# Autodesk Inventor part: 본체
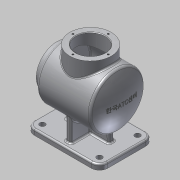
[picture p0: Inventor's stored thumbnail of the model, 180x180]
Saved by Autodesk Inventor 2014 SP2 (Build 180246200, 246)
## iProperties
Created: 2016-09
Part Number: 본체
Material: 알루미늄 6061
Document SubType Name: Modeling
Designer: 1sil_ho3333
Density: 2.71 g/cm^3
Appearance: 알루미늄 - 평지
Mass: 972.342 g
Surface Area: 1283.14 cm^2
Volume: 358.798 cm^3
Author: 1sil_ho3333
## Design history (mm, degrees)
sketch "스케치2"
  geometry: L1 (-61, 0)-(61, 0); L2 (61, 0)-(61, -38); L3 (61, -38)-(49, -38); L4 (49, -38)-(49, -50); L5 (49, -50)-(-49.562, -50); A1 r 115 centre (54, 0) between (-61, 0) and (-49.562, -50); 2 further points
  constraints: 10 end point, 2 parallel, 2 perpendicular, 2 point on circle, 1 centre point, 1 coincident, 1 horizontal, 1 midpoint, 1 point on line
  dimensions: "d4" = 122 distance of L1.start L1.end; "d5" = 100 diameter of L5 L1; "d6" = 76 diameter of L3 L1; "d8" = 115 radius of A1; "d9" = 12 distance of L2.end L3.end
revolve "회전1" sketch "스케치2" stored, may be unused: angle "d10" = 90 deg
node "작업 평면1"
sketch "스케치3"
  geometry: L1 (-67.5, -50)-(67.5, -50); L2 (67.5, -50)-(67.5, 50); L3 (67.5, 50)-(-67.5, 50); L4 (-67.5, 50)-(-67.5, -50); 3 further points
  constraints: 8 end point, 2 midpoint, 2 parallel, 1 horizontal, 1 horizontal alignment, 1 perpendicular, 1 vertical alignment
  dimensions: "d12" = 100 distance of L1.end L2.end; "d13" = 135 distance of L2.end L3.end
extrude "돌출2" join sketch "스케치3" distance "d14" = 10; taper "d15" = 0 deg
node "작업 평면2"
sketch "스케치4"
  geometry: L1 (-61, -38)-(-61, 38) reference; L2 (-61, 0)-(61, 0); L3 (-61, 0)-(-61, 27); L4 (-61, 27)-(-46, 27); L5 (-46, 27)-(-46, 47); L6 (-46, 47)-(47.661, 47); L7 (-49, 50)-(49.562, 50) reference; L8 (-49, -50)-(-49, 50) reference; A1 r 115 centre (-54, 0) between (49.562, -50) and (49.562, 50) reference; A2 r 112 centre (-54, 0) between (58, 0) and (47.661, 47); 1 further point
  constraints: 10 end point, 3 point on circle, 2 perpendicular, 2 point on line, 1 centre point, 1 midpoint, 1 parallel
  dimensions: "d17" = 3 radial gap between concentric circles of A1 A2; "d18" = 3 distance between parallel lines of L7 L6; "d19" = 3 distance between parallel lines of L8 L5; "d20" = 54 diameter of L4 L2
revolve "회전2" sketch "스케치4" stored, may be unused: angle "d21" = 90 deg
fillet "모깎기1" dims "d22" = 2
chamfer "모따기1" distance "d23" = 1; stored, may be unused: second distance "d24" = 2, angle "d25" = 45 deg
sketch "스케치5"
  geometry: L1 (61, 38)-(61, -38) reference; C1 r 38 at (-1, 0); 1 further point
  constraints: 1 centre point
  dimensions: "d26" = 76 diameter of C1; "d28" = 62 distance from line of C1.centre L1
extrude "돌출3" join sketch "스케치5" stored distance "d29" = 10; taper "d30" = 0 deg
sketch "스케치6"
  geometry: C1 r 38 at (0, 0) reference; C2 r 27 at (0, 0); 1 further point
  constraints: 1 centre point, 1 coincident
  dimensions: "d31" = 54 diameter of C2
extrude "돌출4" cut sketch "스케치6" stored distance "d32" = 10; taper "d33" = 0 deg
fillet "모깎기2" dims "d34" = 5
fillet "모깎기3" dims "d35" = 3
chamfer "모따기2" distance "d36" = 1; stored, may be unused: second distance "d37" = 2, angle "d38" = 45 deg
sketch "스케치7"
  geometry: L1 (-40, -5)-(40, -5); L2 (40, -5)-(40, 5); L3 (40, 5)-(-40, 5); L4 (-40, 5)-(-40, -5); L5 (-5, -40)-(5, -40); L6 (5, -40)-(5, 40); L7 (5, 40)-(-5, 40); L8 (-5, 40)-(-5, -40); 5 further points
  constraints: 16 end point, 4 midpoint, 4 parallel, 2 horizontal, 2 horizontal alignment, 2 perpendicular, 2 vertical alignment
  dimensions: "d39" = 10 distance of L6.end L7.end; "d40" = 10 distance of L1.end L2.end; "d41" = 80 distance of L1.start L1.end; "d42" = 80 distance of L5.end L6.end
extrude "돌출6" join sketch "스케치7" stored distance "d45" = 10; taper "d46" = 0 deg
sketch "스케치8"
  geometry: L1 (-40, -72)-(-37.962, -48.7); L2 (-37.962, -48.7)-(37.962, -48.7); L3 (37.962, -48.7)-(40, -72); L4 (40, -72)-(-40, -72); L5 (67.5, -72)-(-67.5, -72) reference; L6 (-44, -50)-(46.374, -50) reference; L7 (-67.5, -82)-(-67.5, -72) reference; L8 (67.5, -82)-(67.5, -72) reference; 2 further points
  constraints: 8 end point, 2 midpoint, 1 horizontal, 1 parallel
  dimensions: "d47" = 95 deg angle of L4 L3; "d48" = 95 deg angle of L4 L1; "d49" = 1.3 distance between parallel lines of L2 L6; "d52" = 80 distance of L3.end L1.start
extrude "돌출7" join sketch "스케치8" stored distance "d50" = 10; taper "d51" = 0 deg
fillet "모깎기4" dims "d53" = 15
fillet "모깎기5" dims "d54" = 3
hole "구멍1" diameter "d57" = 10; stored, may be unused: countersink angle "d61" = 90 deg, drill point angle "d63" = 118 deg; dims "d55" = 10, "d56" = 10, "d58" = 6, "d59" = 4, "d60" = 2, "d62" = 8
fillet "모깎기6" dims "d70" = 3
fillet "모깎기7" dims "d71" = 3
sketch "스케치10" dims "d72" = 65
  geometry: L1 (0, 0)-(0, 32.5); C1 r 28 at (0, 0) reference
  constraints: 2 end point, 1 coincident, 1 vertical, 1 vertical alignment, 2 other
hole "구멍2" sketch "스케치10" at (0, 32.5) diameter "d73" = 3.242; stored, may be unused: countersink angle "d77" = 82 deg, drill point angle "d79" = 118 deg; dims "d74" = 8, "d75" = 3.023, "d76" = 2, "d78" = 10
sketch "스케치11" dims "d83" = 65
  geometry: L1 (0, 0)-(0, 32.5); C1 r 28 at (0, 0) reference; 1 further point
  constraints: 2 end point, 1 coincident, 1 vertical, 1 vertical alignment, 2 other
hole "구멍3" sketch "스케치11" at (0, 32.5) diameter "d84" = 3.242; stored, may be unused: countersink angle "d88" = 82 deg, drill point angle "d90" = 118 deg; dims "d85" = 8, "d86" = 3.023, "d87" = 2, "d89" = 10
node "작업 평면5"
sketch "스케치13"
  geometry: 2 further points
  constraints: 2 coincident, 1 other
feature "엠보싱1" sketch "스케치13" dims "d96" = 0.5, "d97" = 0
node "솔리드2"
pattern_linear "직사각형 패턴1" dims "d66" = 70, "d69" = 105
pattern_circular "원형 패턴1" dims angle "d81" = 360 deg
pattern_circular "원형 패턴2" dims angle "d92" = 360 deg
other parameters: "d11" = -82, "d16" = 147, "d95" = 131.75
